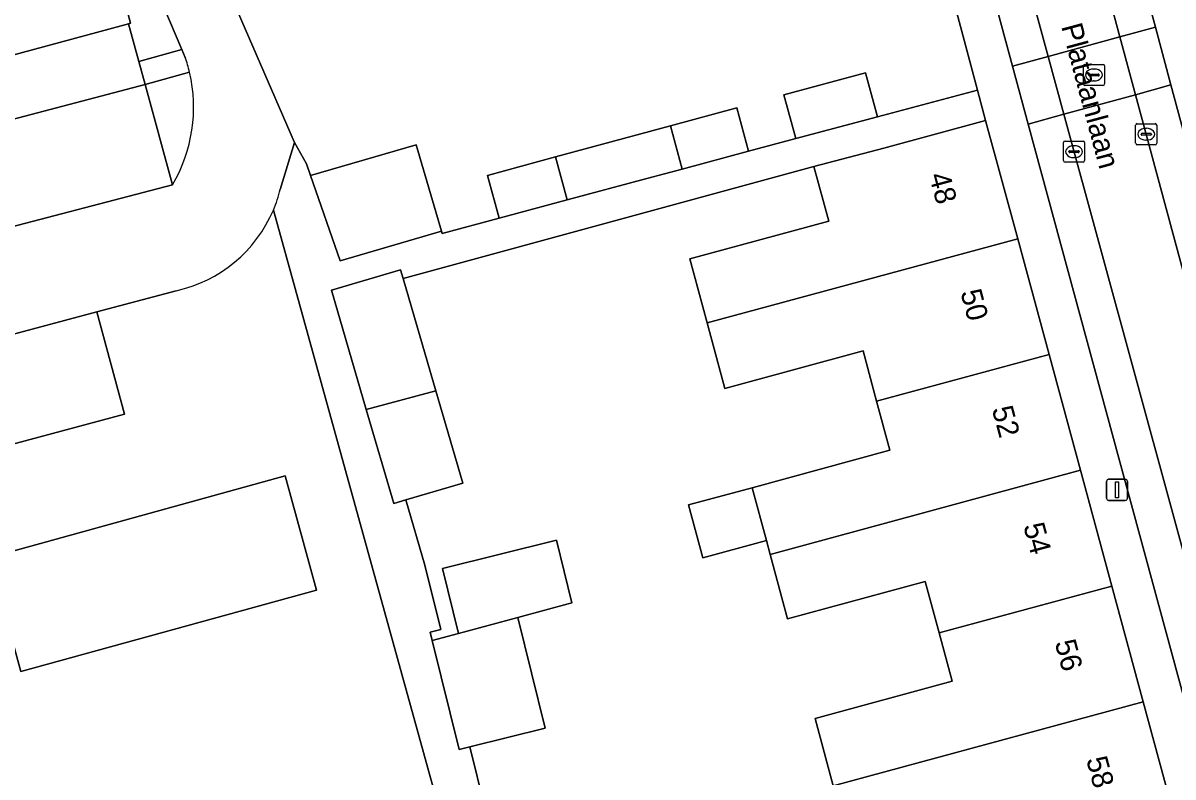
# Model space of a CAD drawing. Extents: x 159262 to 160143, y 383399 to 384319.
# Drawn here: x 159776.1 to 159830.6, y 383753.3 to 383789 of the extents above; entities that cross this region are included whole.
import ezdxf

# ---------------------------------------------------------------- set-up
doc = ezdxf.new("R2010")
doc.units = 0
for name, color, linetype in [('IMGEO_Erf', 7, 'Continuous'), ('IMGEO_Groenvoorziening', 7, 'Continuous'), ('IMGEO_Kolk', 7, 'Continuous'), ('IMGEO_Lichtmast', 7, 'Continuous'), ('IMGEO_Openbare_ruimte_label', 7, 'Continuous'), ('IMGEO_Pand', 7, 'Continuous'), ('IMGEO_Pand_nummerreeks', 7, 'Continuous'), ('IMGEO_Parkeervlak_open', 7, 'Continuous'), ('IMGEO_Rijbaan_lokaal_open', 7, 'Continuous'), ('IMGEO_Rioolput', 7, 'Continuous'), ('IMGEO_Voetpad_open', 7, 'Continuous')]:
    doc.layers.add(name, color=color, linetype=linetype)

msp = doc.modelspace()

# ---------------------------------------------------------------- linework, layer by layer
at = {"layer": 'IMGEO_Erf'}
for points in [[(159783.924, 383794.951), (159788.976, 383783.333), (159789.535, 383782.319), (159789.727, 383781.768), (159794.737, 383783.232), (159795.935, 383779.135), (159795.967, 383779.024), (159798.664, 383779.749), (159798.115, 383781.78), (159801.339, 383782.655), (159806.777, 383784.13), (159809.922, 383784.983), (159810.479, 383782.923), (159812.716, 383783.52), (159812.155, 383785.589), (159816.02, 383786.637), (159816.585, 383784.553), (159821.328, 383785.819), (159818.261, 383797.305)], [(159773.175, 383783.795), (159781.898, 383786.077), (159781.597, 383787.177), (159781.108, 383788.959), (159780.936, 383788.912), (159761.935, 383783.772)], [(159814.481, 383752.879), (159813.64, 383756.072), (159820.123, 383757.831), (159819.502, 383760.122), (159818.842, 383762.558), (159812.328, 383760.791), (159811.501, 383763.837), (159811.323, 383764.495), (159808.317, 383763.679), (159807.639, 383766.182), (159810.645, 383766.997), (159817.177, 383768.768), (159816.548, 383771.088), (159815.902, 383773.47), (159809.359, 383771.696), (159808.52, 383774.793), (159807.696, 383777.83), (159814.278, 383779.614), (159813.577, 383782.2), (159794.119, 383776.895), (159795.672, 383771.584), (159796.95, 383767.214), (159794.24, 383766.421), (159795.144, 383763.33), (159795.898, 383760.28), (159795.393, 383760.156), (159795.492, 383759.758), (159796.737, 383760.093), (159795.975, 383763.177), (159801.376, 383764.511), (159802.11, 383761.541), (159799.553, 383760.852), (159800.847, 383755.618), (159797.269, 383754.734), (159800.11, 383743.243)], [(159772.252, 383738.018), (159777.235, 383738.432), (159793.961, 383739.822), (159799.786, 383718.769), (159802.156, 383710.204), (159806.46, 383694.647), (159813.879, 383667.834), (159815.753, 383668.349), (159820.397, 383651.477), (159821.724, 383646.656), (159822.134, 383645.162), (159822.262, 383644.698), (159825.415, 383645.6), (159821.422, 383659.561), (159819.195, 383667.349), (159787.968, 383780.138)], [(159783.368, 383776.323), (159779.6, 383775.323), (159780.908, 383770.484), (159772.78, 383768.306)]]:
    msp.add_lwpolyline(points, dxfattribs=at)
msp.add_lwpolyline([(159774.518, 383763.7), (159788.526, 383767.561), (159790.017, 383762.152), (159776.009, 383758.292)], close=True, dxfattribs=at)
msp.add_arc((159781.971, 383782.688), 6.517, 282.3777, 336.9634, dxfattribs=at)
at = {"layer": 'IMGEO_Groenvoorziening'}
msp.add_lwpolyline([(159777.945, 383801.127), (159781.205, 383788.985), (159781.108, 383788.959), (159781.597, 383787.177), (159783.633, 383787.743)], close=True, dxfattribs=at)
msp.add_lwpolyline([(159783.997, 383786.66), (159781.898, 383786.077), (159783.196, 383781.338)], dxfattribs=at)
msp.add_arc((159776.939, 383785.001), 7.25, 329.6544, 13.2273, dxfattribs=at)
at = {"layer": 'IMGEO_Kolk'}
for p, q in [((159828.893, 383784.228), (159829.745, 383784.228)), ((159828.818, 383783.302), (159828.818, 383784.154)), ((159829.077, 383783.722), (159829.077, 383783.734)), ((159829.515, 383783.685), (159829.117, 383783.685)), ((159829.12, 383783.771), (159829.518, 383783.771)), ((159829.306, 383784.008), (159829.331, 383784.008)), ((159829.561, 383783.734), (159829.561, 383783.722)), ((159829.819, 383784.154), (159829.819, 383783.302)), ((159825.399, 383782.477), (159825.399, 383783.329)), ((159825.474, 383783.403), (159826.326, 383783.403)), ((159825.887, 383783.183), (159825.912, 383783.183)), ((159826.4, 383783.329), (159826.4, 383782.477)), ((159829.745, 383783.228), (159828.893, 383783.228)), ((159829.329, 383783.448), (159829.304, 383783.448)), ((159825.658, 383782.897), (159825.658, 383782.909)), ((159826.096, 383782.86), (159825.698, 383782.86)), ((159825.701, 383782.946), (159826.099, 383782.946)), ((159825.91, 383782.623), (159825.885, 383782.623)), ((159826.142, 383782.909), (159826.142, 383782.897)), ((159826.326, 383782.403), (159825.474, 383782.403))]:
    msp.add_line(p, q, dxfattribs=at)
for points in [[(159828.893, 383784.228), (159829.745, 383784.228)], [(159828.818, 383783.302), (159828.818, 383784.154)], [(159829.819, 383784.154), (159829.819, 383783.302)], [(159825.399, 383782.477), (159825.399, 383783.329)], [(159825.474, 383783.403), (159826.326, 383783.403)], [(159826.4, 383783.329), (159826.4, 383782.477)], [(159829.745, 383783.228), (159828.893, 383783.228)], [(159826.326, 383782.403), (159825.474, 383782.403)]]:
    msp.add_lwpolyline(points, dxfattribs=at)
for centre, radius, start, end in [((159828.895, 383784.152), 0.0765, 91.552, 178.448), ((159828.895, 383784.152), 0.0765, 91.552, 178.448), ((159829.743, 383784.152), 0.0765, 1.552, 88.448), ((159829.743, 383784.152), 0.0765, 1.552, 88.448), ((159829.117, 383783.731), 0.0403, 85.8775, 175.7526), ((159829.114, 383783.721), 0.0366, 178.938, 274.7102), ((159829.518, 383783.728), 0.043, 264.8664, 352.4533), ((159829.522, 383783.733), 0.0386, 1.7309, 96.639), ((159825.476, 383783.327), 0.0765, 91.552, 178.448), ((159825.476, 383783.327), 0.0765, 91.552, 178.448), ((159826.324, 383783.327), 0.0765, 1.552, 88.448), ((159826.324, 383783.327), 0.0765, 1.552, 88.448), ((159828.895, 383783.304), 0.0765, 181.552, 268.448), ((159828.895, 383783.304), 0.0765, 181.552, 268.448), ((159829.743, 383783.304), 0.0765, 271.552, 358.448), ((159829.743, 383783.304), 0.0765, 271.552, 358.448), ((159825.698, 383782.906), 0.0403, 85.8775, 175.7526), ((159825.695, 383782.896), 0.0366, 178.938, 274.7102), ((159826.099, 383782.903), 0.043, 264.8664, 352.4533), ((159826.103, 383782.908), 0.0386, 1.7309, 96.639), ((159825.476, 383782.479), 0.0765, 181.552, 268.448), ((159825.476, 383782.479), 0.0765, 181.552, 268.448), ((159826.324, 383782.479), 0.0765, 271.552, 358.448), ((159826.324, 383782.479), 0.0765, 271.552, 358.448)]:
    msp.add_arc(centre, radius, start, end, dxfattribs=at)
for centre, major_axis, ratio, start_param, end_param in [((159829.305, 383783.728), (-0.387, 0.002), 0.722429, 4.712389, 7.853982), ((159829.33, 383783.728), (-0.39, 0.002), 0.717154, 1.570796, 4.712389), ((159825.886, 383782.903), (-0.387, 0.002), 0.722429, 4.712389, 7.853982), ((159825.911, 383782.903), (-0.39, 0.002), 0.717154, 1.570796, 4.712389)]:
    msp.add_ellipse(centre, major_axis=major_axis, ratio=ratio, start_param=start_param, end_param=end_param, dxfattribs=at)
at = {"layer": 'IMGEO_Lichtmast'}
for p, q in [((159827.537, 383767.397), (159828.327, 383767.397)), ((159828.327, 383767.397), (159827.537, 383767.397)), ((159827.437, 383766.497), (159827.437, 383767.297)), ((159827.437, 383767.297), (159827.437, 383766.497)), ((159828.427, 383767.297), (159828.427, 383766.497)), ((159828.427, 383766.497), (159828.427, 383767.297)), ((159828.327, 383766.397), (159827.537, 383766.397)), ((159827.537, 383766.397), (159828.327, 383766.397))]:
    msp.add_line(p, q, dxfattribs=at)
msp.add_lwpolyline([(159827.857, 383767.272), (159828.007, 383767.272), (159828.007, 383766.522), (159827.857, 383766.522), (159827.857, 383767.272)], dxfattribs=at)
for centre, start, end in [((159827.537, 383767.297), 90, 180), ((159827.537, 383767.297), 90, 180), ((159828.327, 383767.297), 0, 90), ((159828.327, 383767.297), 360, 90), ((159827.537, 383766.497), 180, 270), ((159827.537, 383766.497), 180, 270), ((159828.327, 383766.497), 270, 0), ((159828.327, 383766.497), 270, 0)]:
    msp.add_arc(centre, 0.1, start, end, dxfattribs=at)
at = {"layer": 'IMGEO_Pand'}
for points in [[(159777.945, 383801.127), (159777.726, 383801.942), (159759.022, 383796.872), (159758.307, 383796.678), (159761.098, 383786.327), (159761.798, 383783.735), (159761.935, 383783.772), (159780.936, 383788.912), (159781.108, 383788.959), (159781.205, 383788.985)], [(159812.155, 383785.589), (159812.716, 383783.52), (159816.585, 383784.553), (159816.02, 383786.637)], [(159807.332, 383782.082), (159810.479, 383782.923), (159809.922, 383784.983), (159806.777, 383784.13)], [(159821.712, 383784.379), (159816.894, 383783.072), (159813.577, 383782.2), (159814.278, 383779.614), (159807.696, 383777.83), (159808.52, 383774.793), (159823.23, 383778.783)], [(159806.777, 383784.13), (159801.339, 383782.655), (159801.891, 383780.616), (159805.667, 383781.638), (159807.332, 383782.082)], [(159789.727, 383781.768), (159791.135, 383777.731), (159795.935, 383779.135), (159794.737, 383783.232)], [(159801.339, 383782.655), (159798.115, 383781.78), (159798.664, 383779.749), (159801.891, 383780.616)], [(159823.23, 383778.783), (159808.52, 383774.793), (159809.359, 383771.696), (159815.902, 383773.47), (159816.548, 383771.088), (159824.715, 383773.303)], [(159794.119, 383776.895), (159793.998, 383777.309), (159790.717, 383776.349), (159792.371, 383770.694), (159795.672, 383771.584)], [(159824.715, 383773.303), (159816.548, 383771.088), (159817.177, 383768.768), (159810.645, 383766.997), (159811.323, 383764.495), (159811.501, 383763.837), (159826.201, 383767.824)], [(159795.672, 383771.584), (159792.371, 383770.694), (159793.669, 383766.254), (159794.24, 383766.421), (159796.95, 383767.214)], [(159776.009, 383758.292), (159790.017, 383762.152), (159788.526, 383767.561), (159774.518, 383763.7)], [(159826.201, 383767.824), (159811.501, 383763.837), (159812.328, 383760.791), (159818.842, 383762.558), (159819.502, 383760.122), (159827.686, 383762.343)], [(159810.645, 383766.997), (159807.639, 383766.182), (159808.317, 383763.679), (159811.323, 383764.495)], [(159795.975, 383763.177), (159796.737, 383760.093), (159799.553, 383760.852), (159802.11, 383761.541), (159801.376, 383764.511)], [(159827.686, 383762.343), (159819.502, 383760.122), (159820.123, 383757.831), (159813.64, 383756.072), (159814.481, 383752.879), (159829.171, 383756.863)], [(159799.553, 383760.852), (159796.737, 383760.093), (159795.492, 383759.758), (159796.765, 383754.609), (159797.269, 383754.734), (159800.847, 383755.618)], [(159830.688, 383751.271), (159829.171, 383756.863), (159814.481, 383752.879), (159815.288, 383749.819), (159815.336, 383749.637), (159816.013, 383749.82), (159821.779, 383751.378), (159822.205, 383749.83), (159822.428, 383749.02), (159825.449, 383749.835), (159825.874, 383749.949)]]:
    msp.add_lwpolyline(points, close=True, dxfattribs=at)
at = {"layer": 'IMGEO_Parkeervlak_open'}
for points in [[(159821.154, 383813.948), (159825.176, 383799.06), (159828.074, 383788.332), (159829.752, 383788.79), (159826.858, 383799.486), (159823.489, 383811.938)], [(159816.732, 383810.011), (159820.056, 383797.76), (159822.99, 383786.944), (159824.672, 383787.403), (159821.728, 383798.185), (159817.728, 383812.995)], [(159838.164, 383757.704), (159830.491, 383786.059), (159828.812, 383785.6), (159837.167, 383754.668)], [(159833.909, 383753.582), (159825.418, 383784.673), (159823.731, 383784.212), (159831.459, 383755.725)]]:
    msp.add_lwpolyline(points, dxfattribs=at)
for points in [[(159828.812, 383785.6), (159830.491, 383786.059), (159829.752, 383788.79), (159828.074, 383788.332)], [(159823.731, 383784.212), (159825.418, 383784.673), (159824.672, 383787.403), (159822.99, 383786.944)], [(159781.898, 383786.077), (159773.175, 383783.795), (159774.465, 383779.054), (159783.196, 383781.338)], [(159772.78, 383768.306), (159780.908, 383770.484), (159779.6, 383775.323), (159759.683, 383769.988), (159761.023, 383765.091), (159761.129, 383765.119), (159772.808, 383768.178)]]:
    msp.add_lwpolyline(points, close=True, dxfattribs=at)
at = {"layer": 'IMGEO_Rijbaan_lokaal_open'}
for points in [[(159817.391, 383814.24), (159817.728, 383812.995), (159821.728, 383798.185), (159824.672, 383787.403), (159828.074, 383788.332), (159825.176, 383799.06), (159821.154, 383813.948), (159821.106, 383814.126), (159820.841, 383815.179)], [(159828.812, 383785.6), (159828.074, 383788.332), (159824.672, 383787.403), (159825.418, 383784.673)], [(159828.812, 383785.6), (159825.418, 383784.673), (159833.909, 383753.582), (159837.215, 383754.491), (159837.167, 383754.668)]]:
    msp.add_lwpolyline(points, close=True, dxfattribs=at)
for points in [[(159788.296, 383781.119), (159788.976, 383783.333), (159783.924, 383794.951), (159780.709, 383802.483), (159779.417, 383805.511), (159776.518, 383804.726), (159777.726, 383801.942), (159777.945, 383801.127), (159783.633, 383787.743), (159783.792, 383787.368)], [(159783.196, 383781.338), (159774.465, 383779.054), (159771.67, 383778.29), (159758.384, 383774.731), (159759.683, 383769.988), (159779.6, 383775.323), (159783.368, 383776.323)]]:
    msp.add_lwpolyline(points, dxfattribs=at)
for centre, radius, start, end in [((159776.65, 383784.916), 7.551, 13.3507, 18.9458), ((159776.939, 383785.001), 7.25, 329.6544, 13.2273), ((159782.11, 383782.642), 6.37, 336.8558, 346.1692), ((159781.971, 383782.688), 6.517, 282.3777, 336.9634)]:
    msp.add_arc(centre, radius, start, end, dxfattribs=at)
at = {"layer": 'IMGEO_Rioolput'}
for p, q in [((159826.342, 383786.107), (159826.342, 383786.959)), ((159826.417, 383787.033), (159827.269, 383787.033)), ((159827.343, 383786.959), (159827.343, 383786.107)), ((159826.601, 383786.527), (159826.601, 383786.539)), ((159827.039, 383786.49), (159826.641, 383786.49)), ((159826.644, 383786.576), (159827.042, 383786.576)), ((159826.83, 383786.813), (159826.855, 383786.813)), ((159827.085, 383786.539), (159827.085, 383786.527)), ((159827.269, 383786.033), (159826.417, 383786.033)), ((159826.853, 383786.253), (159826.828, 383786.253))]:
    msp.add_line(p, q, dxfattribs=at)
for points in [[(159826.342, 383786.107), (159826.342, 383786.959)], [(159826.417, 383787.033), (159827.269, 383787.033)], [(159827.343, 383786.959), (159827.343, 383786.107)], [(159827.269, 383786.033), (159826.417, 383786.033)]]:
    msp.add_lwpolyline(points, dxfattribs=at)
for centre, radius, start, end in [((159826.419, 383786.957), 0.0765, 91.552, 178.448), ((159826.419, 383786.957), 0.0765, 91.552, 178.448), ((159827.267, 383786.957), 0.0765, 1.552, 88.448), ((159827.267, 383786.957), 0.0765, 1.552, 88.448), ((159826.641, 383786.536), 0.0403, 85.8775, 175.7526), ((159826.638, 383786.526), 0.0366, 178.938, 274.7102), ((159827.042, 383786.533), 0.043, 264.8664, 352.4533), ((159827.046, 383786.538), 0.0386, 1.7309, 96.639), ((159826.419, 383786.109), 0.0765, 181.552, 268.448), ((159826.419, 383786.109), 0.0765, 181.552, 268.448), ((159827.267, 383786.109), 0.0765, 271.552, 358.448), ((159827.267, 383786.109), 0.0765, 271.552, 358.448)]:
    msp.add_arc(centre, radius, start, end, dxfattribs=at)
for centre, major_axis, ratio, start_param, end_param in [((159826.829, 383786.533), (-0.387, 0.002), 0.722429, 4.712389, 7.853982), ((159826.854, 383786.533), (-0.39, 0.002), 0.717154, 1.570796, 4.712389)]:
    msp.add_ellipse(centre, major_axis=major_axis, ratio=ratio, start_param=start_param, end_param=end_param, dxfattribs=at)
at = {"layer": 'IMGEO_Voetpad_open'}
for points in [[(159817.728, 383812.995), (159817.391, 383814.24), (159816.064, 383819.153), (159812.514, 383818.172), (159813.446, 383814.675), (159818.261, 383797.305), (159821.328, 383785.819), (159821.712, 383784.379), (159823.23, 383778.783), (159824.715, 383773.303), (159826.201, 383767.824), (159827.686, 383762.343), (159829.171, 383756.863), (159830.688, 383751.271)], [(159823.489, 383811.938), (159826.858, 383799.486), (159829.752, 383788.79), (159830.491, 383786.059), (159838.164, 383757.704)], [(159831.459, 383755.725), (159823.731, 383784.212), (159822.99, 383786.944), (159820.056, 383797.76), (159816.732, 383810.011)], [(159783.792, 383787.368), (159783.633, 383787.743), (159781.597, 383787.177), (159781.898, 383786.077), (159783.997, 383786.66)], [(159813.577, 383782.2), (159816.894, 383783.072), (159821.712, 383784.379), (159821.328, 383785.819), (159816.585, 383784.553), (159812.716, 383783.52), (159810.479, 383782.923), (159807.332, 383782.082), (159805.667, 383781.638), (159801.891, 383780.616), (159798.664, 383779.749), (159795.967, 383779.024), (159795.935, 383779.135), (159791.135, 383777.731), (159789.727, 383781.768), (159789.535, 383782.319), (159788.976, 383783.333), (159788.296, 383781.119)], [(159800.11, 383743.243), (159797.269, 383754.734), (159796.765, 383754.609), (159795.492, 383759.758), (159795.393, 383760.156), (159795.898, 383760.28), (159795.144, 383763.33), (159794.24, 383766.421), (159793.669, 383766.254), (159792.371, 383770.694), (159790.717, 383776.349), (159793.998, 383777.309), (159794.119, 383776.895), (159813.577, 383782.2)], [(159787.968, 383780.138), (159819.195, 383667.349)]]:
    msp.add_lwpolyline(points, dxfattribs=at)
for centre, radius, start, end in [((159776.65, 383784.916), 7.551, 13.3507, 18.9458), ((159782.11, 383782.642), 6.37, 336.8558, 346.1692)]:
    msp.add_arc(centre, radius, start, end, dxfattribs=at)

# ---------------------------------------------------------------- texts
at = {"layer": 'IMGEO_Openbare_ruimte_label'}
msp.add_text('Plataanlaan', height=1, rotation=285.0642, dxfattribs=at).set_placement((159825.284, 383788.838))
at = {"layer": 'IMGEO_Pand_nummerreeks'}
for s, p in [('48', (159819.02, 383781.778)), ('50', (159820.509, 383776.25)), ('52', (159821.998, 383770.727)), ('54', (159823.487, 383765.196)), ('56', (159824.977, 383759.667)), ('58', (159826.467, 383754.136))]:
    msp.add_text(s, height=1, rotation=285.08, dxfattribs=at).set_placement(p)

doc.saveas('drawing.dxf')
